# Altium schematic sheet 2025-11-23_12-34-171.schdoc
size 471 x 212 mm; SheetNumber: 1; SheetTotal: 1
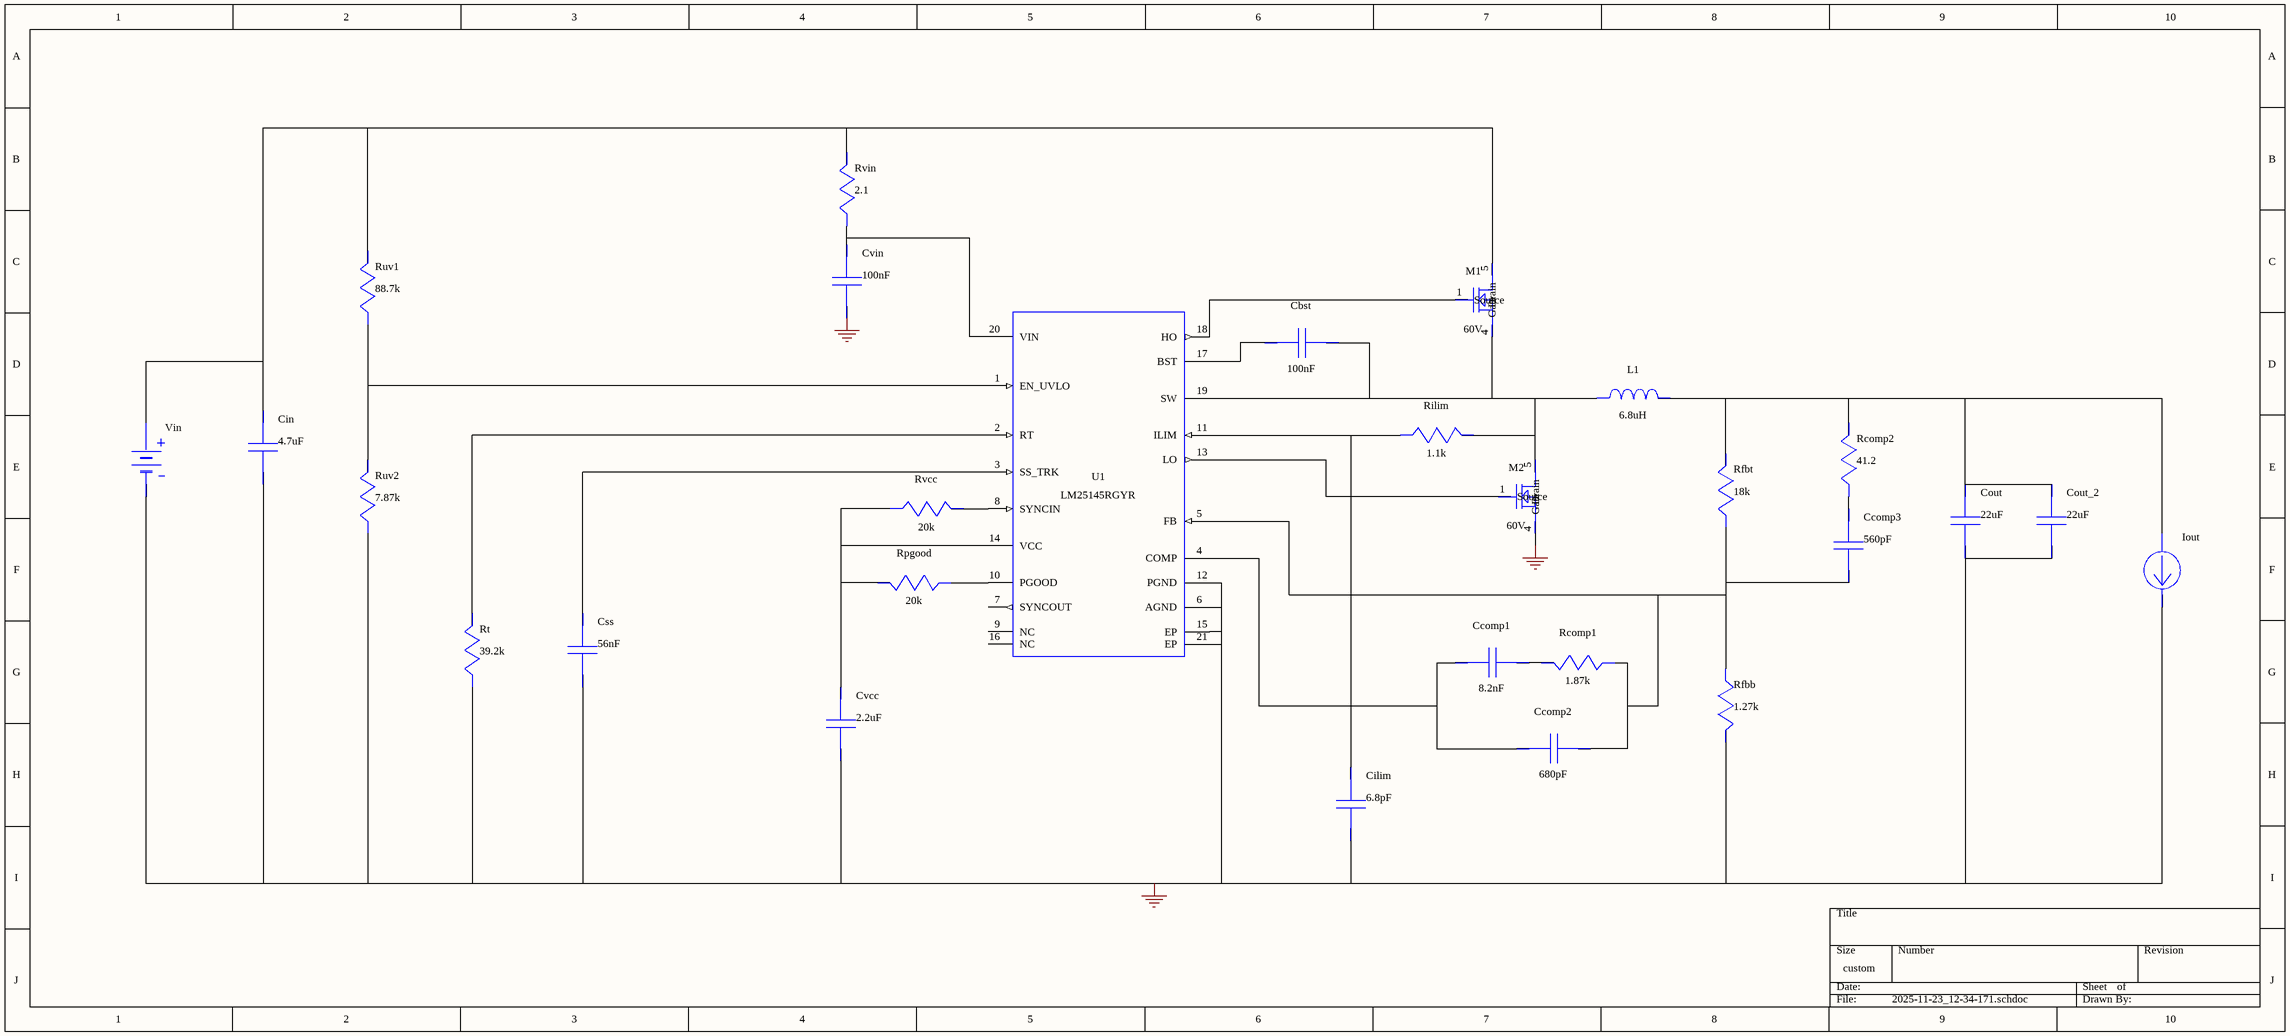
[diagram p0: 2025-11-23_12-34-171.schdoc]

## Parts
Cbst  value 100nF  (hidden comment: CGA3E2X7R1H104K080AA)
Ccomp1  value 8.2nF  (hidden comment: GRM155R71C822KA01D)
Ccomp2  value 680pF  (hidden comment: CGA2B2X7R1H681K050BA)
Ccomp3  value 560pF  (hidden comment: GRM155R71H561KA01D)
Cilim  value 6.8pF  (hidden comment: 06031U6R8BAT2A)
Cin  value 4.7uF  (hidden comment: MSASU32MSB7475MPNA01)
Cout  value 22uF  (hidden comment: MSAST32MSB7226KPNB25)
Cout_2  value 22uF  (hidden comment: MSAST32MSB7226KPNB25)
Css  value 56nF  (hidden comment: GRM155R71C563KA88D)
Cvcc  value 2.2uF  (hidden comment: CGA5L2X7R1E225K160AA)
Cvin  value 100nF  (hidden comment: CGA3E2X7R1H104K080AA)
Iout  WB_CURRENT_LOAD  (value not drawn)
L1  value 6.8uH  (hidden comment: SRP1270-6R8M)
M1  value 60V  (hidden comment: CSD18543Q3A)
M2  value 60V  (hidden comment: CSD18543Q3A)
Rcomp1  value 1.87k  (hidden comment: CRCW04021K87FKED)
Rcomp2  value 41.2  (hidden comment: CRCW040241R2FKED)
Rfbb  value 1.27k  (hidden comment: CRCW04021K27FKED)
Rfbt  value 18k  (hidden comment: RC0603FR-0718KL)
Rilim  value 1.1k  (hidden comment: CRCW04021K10FKED)
Rpgood  value 20k  (hidden comment: RC0603FR-0720KL)
Rt  value 39.2k  (hidden comment: CRCW040239K2FKED)
Ruv1  value 88.7k  (hidden comment: CRCW040288K7FKED)
Ruv2  value 7.87k  (hidden comment: RC0603FR-077K87L)
Rvcc  value 20k  (hidden comment: RC0603FR-0720KL)
Rvin  value 2.1  (hidden comment: CRCW06032R10FKEA)
U1  LM25145RGYR
Vin  WB_BATTERY  (value not drawn)

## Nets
0: Cilim.1 Cin.2 Cout.2 Cout_2.2 Css.2 Cvcc.2 Cvin.2 Iout.2(-) M2.4(Gate) Rfbb.1 Rt.2 Ruv2.2 U1.6(AGND) U1.12(PGND) U1.15(EP) U1.21(EP) Vin.2(-)
NetCbst_1: Cbst.1 U1.17(BST)
NetCbst_2: Cbst.2 L1.2 M1.4(Gate) M2.5(Drain) M2.6(Drain) M2.7(Drain) M2.8(Drain) M2.9(Drain) Rilim.1 U1.19(SW)
NetCcomp1_1: Ccomp1.1 Ccomp2.1 U1.4(COMP)
NetCcomp1_2: Ccomp1.2 Rcomp1.1
NetCcomp2_2: Ccomp2.2 Ccomp3.2 Rcomp1.2 Rfbb.2 Rfbt.2 U1.5(FB)
NetCcomp3_1: Ccomp3.1 Rcomp2.2
NetCilim_2: Cilim.2 Rilim.2 U1.11(ILIM)
NetCin_1: Cin.1 M1.5(Drain) M1.6(Drain) M1.7(Drain) M1.8(Drain) M1.9(Drain) Ruv1.1 Rvin.1 Vin.1(+)
NetCout_1: Cout.1 Cout_2.1 Iout.1(+) L1.1 Rcomp2.1 Rfbt.1
NetCss_1: Css.1 U1.3(SS_TRK)
NetCvcc_1: Cvcc.1 Rpgood.1 Rvcc.2 U1.14(VCC)
NetCvin_1: Cvin.1 Rvin.2 U1.20(VIN)
NetM1_1: M1.1(Source) M1.2(Source) M1.3(Source) U1.18(HO)
NetM2_1: M2.1(Source) M2.2(Source) M2.3(Source) U1.13(LO)
NetRpgood_2: Rpgood.2 U1.10(PGOOD)
NetRt_1: Rt.1 U1.2(RT)
NetRuv1_2: Ruv1.2 Ruv2.1 U1.1(EN_UVLO)
NetRvcc_1: Rvcc.1 U1.8(SYNCIN)

Not connected (* = marked no-connect by the designer): U1 7(SYNCOUT) 9(NC) 16(NC)

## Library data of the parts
Cbst Cvin = CGA3E2X7R1H104K080AA: CGA3E2X7R1H104K0; Manufacturer Name: TDK
Ccomp1 = GRM155R71C822KA01D: GRM155R71C822KA0; Manufacturer Name: MuRata
Ccomp2 = CGA2B2X7R1H681K050BA: CGA2B2X7R1H681K0; Manufacturer Name: TDK
Ccomp3 = GRM155R71H561KA01D: GRM155R71H561KA0; Manufacturer Name: MuRata
Cilim = 06031U6R8BAT2A: Manufacturer Name: AVX
Cin = MSASU32MSB7475MPNA01: MSASU32MSB7475MP; Manufacturer Name: Taiyo Yuden
Cout Cout_2 = MSAST32MSB7226KPNB25: MSAST32MSB7226KP; Manufacturer Name: Taiyo Yuden
Css = GRM155R71C563KA88D: GRM155R71C563KA8; Manufacturer Name: MuRata
Cvcc = CGA5L2X7R1E225K160AA: CGA5L2X7R1E225K1; Manufacturer Name: TDK
L1 = SRP1270-6R8M: Manufacturer Name: Bourns
M1 M2 = CSD18543Q3A: Manufacturer Name: Texas Instruments
Rcomp1 = CRCW04021K87FKED: Manufacturer Name: Vishay-Dale
Rcomp2 = CRCW040241R2FKED: Manufacturer Name: Vishay-Dale
Rfbb = CRCW04021K27FKED: Manufacturer Name: Vishay-Dale
Rfbt = RC0603FR-0718KL: Manufacturer Name: Yageo
Rilim = CRCW04021K10FKED: Manufacturer Name: Vishay-Dale
Rpgood Rvcc = RC0603FR-0720KL: Manufacturer Name: Yageo
Rt = CRCW040239K2FKED: Manufacturer Name: Vishay-Dale
Ruv1 = CRCW040288K7FKED: Manufacturer Name: Vishay-Dale
Ruv2 = RC0603FR-077K87L: Manufacturer Name: Yageo
Rvin = CRCW06032R10FKEA: Manufacturer Name: Vishay-Dale
U1 = LM25145RGYR: Manufacturer Name: Texas Instruments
